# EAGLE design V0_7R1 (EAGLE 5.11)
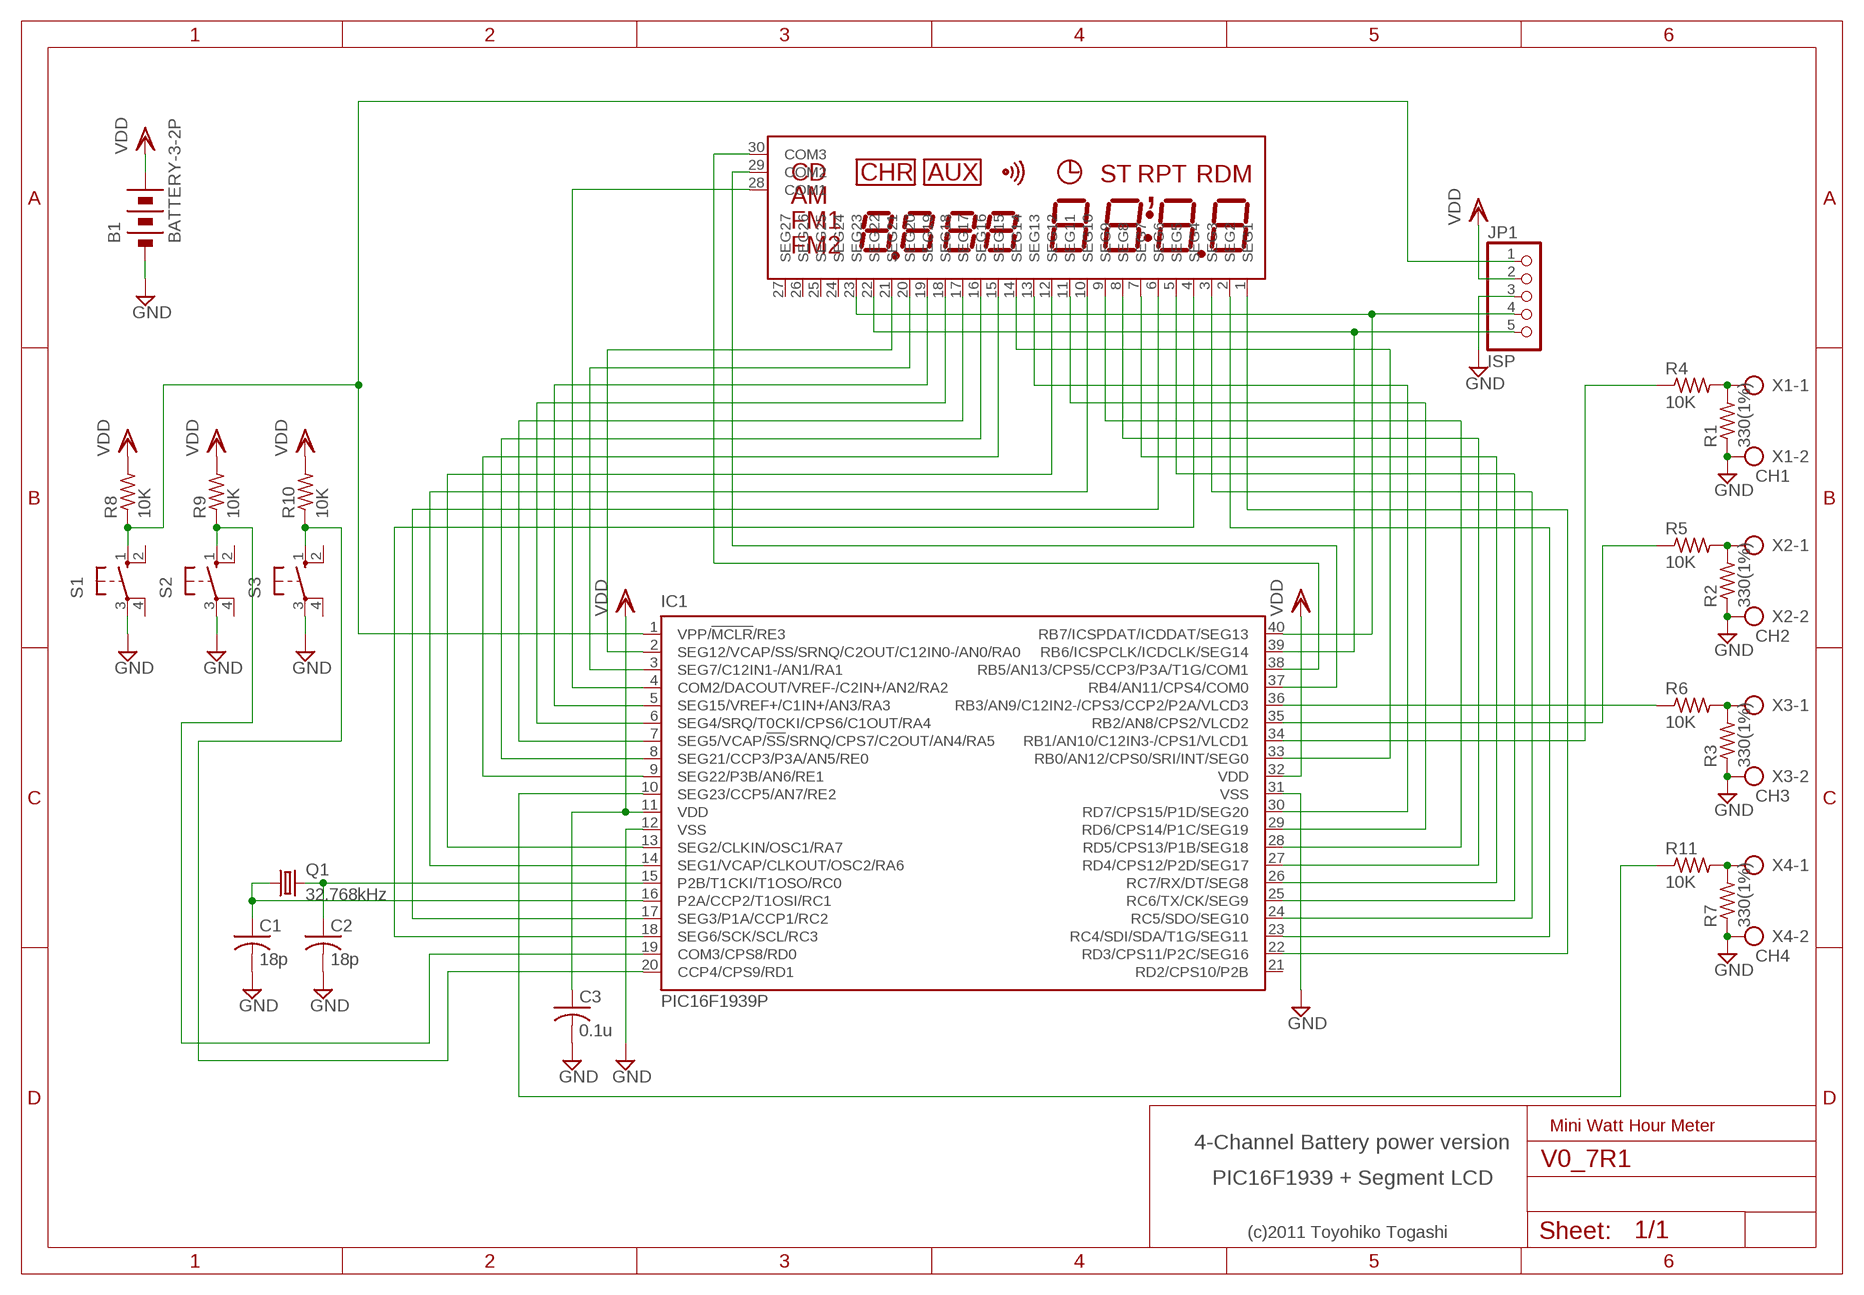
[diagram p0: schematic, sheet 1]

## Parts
B1  BATTERY-3-2P  [CONN-2P]
C1  18p  C-US025-024X044  [C025-024X044]
C2  18p  C-US025-024X044  [C025-024X044]
C3  0.1u  C-US025-024X044  [C025-024X044]
IC1  PIC16F1939P  [DIL40]
JP1  ISP  PINHD-1X5  [1X05]
LCD1  LCD-30P-AITENDO  [LCD-30P-AITENDO]
Q1  32.768kHz  CRYSTALTC38H  [TC38H]
R1  330(1%)  R-US_0204/7  [0204/7]
R2  330(1%)  R-US_0204/7  [0204/7]
R3  330(1%)  R-US_0204/7  [0204/7]
R4  10K  R-US_0204/5  [0204/5]
R5  10K  R-US_0204/5  [0204/5]
R6  10K  R-US_0204/5  [0204/5]
R7  330(1%)  R-US_0204/7  [0204/7]
R8  10K  R-US_0204/5  [0204/5]
R9  10K  R-US_0204/5  [0204/5]
R10  10K  R-US_0204/5  [0204/5]
R11  10K  R-US_0204/5  [0204/5]
S1  10-XX  [B3F-10XX]
S2  10-XX  [B3F-10XX]
S3  10-XX  [B3F-10XX]
X1  CH1  AK300/2  [AK300/2]
X2  CH2  AK300/2  [AK300/2]
X3  CH3  AK300/2  [AK300/2]
X4  CH4  AK300/2  [AK300/2]

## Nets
GND: B1.P$2(MINUS) C1.2 C2.2 C3.2 IC1.12(VSS) IC1.31(VSS) JP1.3 R1.1 R2.1 R3.1 R7.1 S1.3(P) S2.3(P) S3.3(P) X1.2 X2.2 X3.2 X4.2
N$1: IC1.37(RB4/AN11/CPS4/COM0) LCD1.29(COM2)
N$2: IC1.38(RB5/AN13/CPS5/CCP3/P3A/T1G/COM1) LCD1.30(COM3)
N$3: IC1.39(RB6/ICSPCLK/ICDCLK/SEG14) JP1.5 LCD1.22(SEG22)
N$4: IC1.2(SEG12/VCAP/SS/SRNQ/C2OUT/C12IN0-/AN0/RA0) LCD1.21(SEG21)
N$5: IC1.14(SEG1/VCAP/CLKOUT/OSC2/RA6) LCD1.10(SEG10)
N$6: IC1.13(SEG2/CLKIN/OSC1/RA7) LCD1.12(SEG12)
N$7: IC1.17(SEG3/P1A/CCP1/RC2) LCD1.6(SEG6)
N$8: IC1.6(SEG4/SRQ/T0CKI/CPS6/C1OUT/RA4) LCD1.18(SEG18)
N$9: IC1.7(SEG5/VCAP/!SS!/SRNQ/CPS7/C2OUT/AN4/RA5) LCD1.17(SEG17)
N$10: IC1.18(SEG6/SCK/SCL/RC3) LCD1.4(SEG4)
N$11: IC1.22(RD3/CPS11/P2C/SEG16) LCD1.1(SEG1)
N$12: IC1.26(RC7/RX/DT/SEG8) LCD1.7(SEG7)
N$13: IC1.25(RC6/TX/CK/SEG9) LCD1.5(SEG5)
N$14: IC1.24(RC5/SDO/SEG10) LCD1.3(SEG3)
N$15: IC1.23(RC4/SDI/SDA/T1G/SEG11) LCD1.2(SEG2)
N$16: IC1.1(VPP/!MCLR!/RE3) JP1.1 R8.1 S1.1(S)
N$17: R7.2 R11.2 X4.1
N$18: IC1.40(RB7/ICSPDAT/ICDDAT/SEG13) JP1.4 LCD1.23(SEG23)
N$19: IC1.10(SEG23/CCP5/AN7/RE2) R11.1
N$21: IC1.27(RD4/CPS12/P2D/SEG17) LCD1.8(SEG8)
N$22: IC1.28(RD5/CPS13/P1B/SEG18) LCD1.9(SEG9)
N$24: IC1.19(COM3/CPS8/RD0) R9.1 S2.1(S)
N$25: IC1.4(COM2/DACOUT/VREF-/C2IN+/AN2/RA2) LCD1.28(COM1)
N$26: IC1.29(RD6/CPS14/P1C/SEG19) LCD1.11(SEG11)
N$28: IC1.8(SEG21/CCP3/P3A/AN5/RE0) LCD1.16(SEG16)
N$29: IC1.9(SEG22/P3B/AN6/RE1) LCD1.15(SEG15)
N$31: C2.1 IC1.15(P2B/T1CKI/T1OSO/RC0) Q1.2
N$32: C1.1 IC1.16(P2A/CCP2/T1OSI/RC1) Q1.1
N$33: IC1.34(RB1/AN10/C12IN3-/CPS1/VLCD1) R4.1
N$36: IC1.20(CCP4/CPS9/RD1) R10.1 S3.1(S)
N$37: R1.2 R4.2 X1.1
N$38: IC1.33(RB0/AN12/CPS0/SRI/INT/SEG0) LCD1.14(SEG14)
N$39: R2.2 R5.2 X2.1
N$40: IC1.35(RB2/AN8/CPS2/VLCD2) R5.1
N$41: R3.2 R6.2 X3.1
N$42: IC1.36(RB3/AN9/C12IN2-/CPS3/CCP2/P2A/VLCD3) R6.1
N$45: IC1.30(RD7/CPS15/P1D/SEG20) LCD1.13(SEG13)
N$47: IC1.3(SEG7/C12IN1-/AN1/RA1) LCD1.20(SEG20)
N$51: IC1.5(SEG15/VREF+/C1IN+/AN3/RA3) LCD1.19(SEG19)
VDD: B1.P$1(PLUS) C3.1 IC1.11(VDD) IC1.32(VDD) JP1.2 R8.2 R9.2 R10.2
Unconnected: IC1.21(RD2/CPS10/P2B) LCD1.24(SEG24) LCD1.25(SEG25) LCD1.26(SEG26) LCD1.27(SEG27) S1.2(S1) S1.4(P1) S2.2(S1) S2.4(P1) S3.2(S1) S3.4(P1)

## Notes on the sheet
- Mini Watt Hour Meter
- 4-Channel Battery power version
- PIC16F1939 + Segment LCD
- (c)2011 Toyohiko Togashi

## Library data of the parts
B1 = TOG:BATTERY-3: Battery 3cell
C1-C3 = rcl:C-US: CAPACITOR, American symbol
IC1 = microchip:PIC16F193*?: Flash-Based, 8-Bit CMOS Microcontrollers wtih LCD Driver and nanoWatt XLP Technology Auto generated by make-symbol-device-package-bsdl.ulp Rev. 33 Source: http://ww1.microchip.com/downloads/en/DeviceDoc/41364D.pdf; MPN: PIC16F1939-I/P; OC_FARNELL: 1755832; OC_NEWARK: 08R1958
JP1 = pinhead:PINHD-1X5: PIN HEADER
LCD1 = TOG:LCD-30P-AITENDO
Q1 = crystal:CRYSTAL: CRYSTAL; OC_FARNELL: unknown; OC_NEWARK: unknown
R1-R11 = rcl:R-US_: RESISTOR, American symbol
S1-S3 = switch-omron:10-XX: OMRON SWITCH; MPN: B3F-1000; OC_FARNELL: 176432; OC_NEWARK: 36M3542
X1-X4 = con-ptr500:AK300/2: CONNECTOR; OC_FARNELL: unknown; OC_NEWARK: unknown

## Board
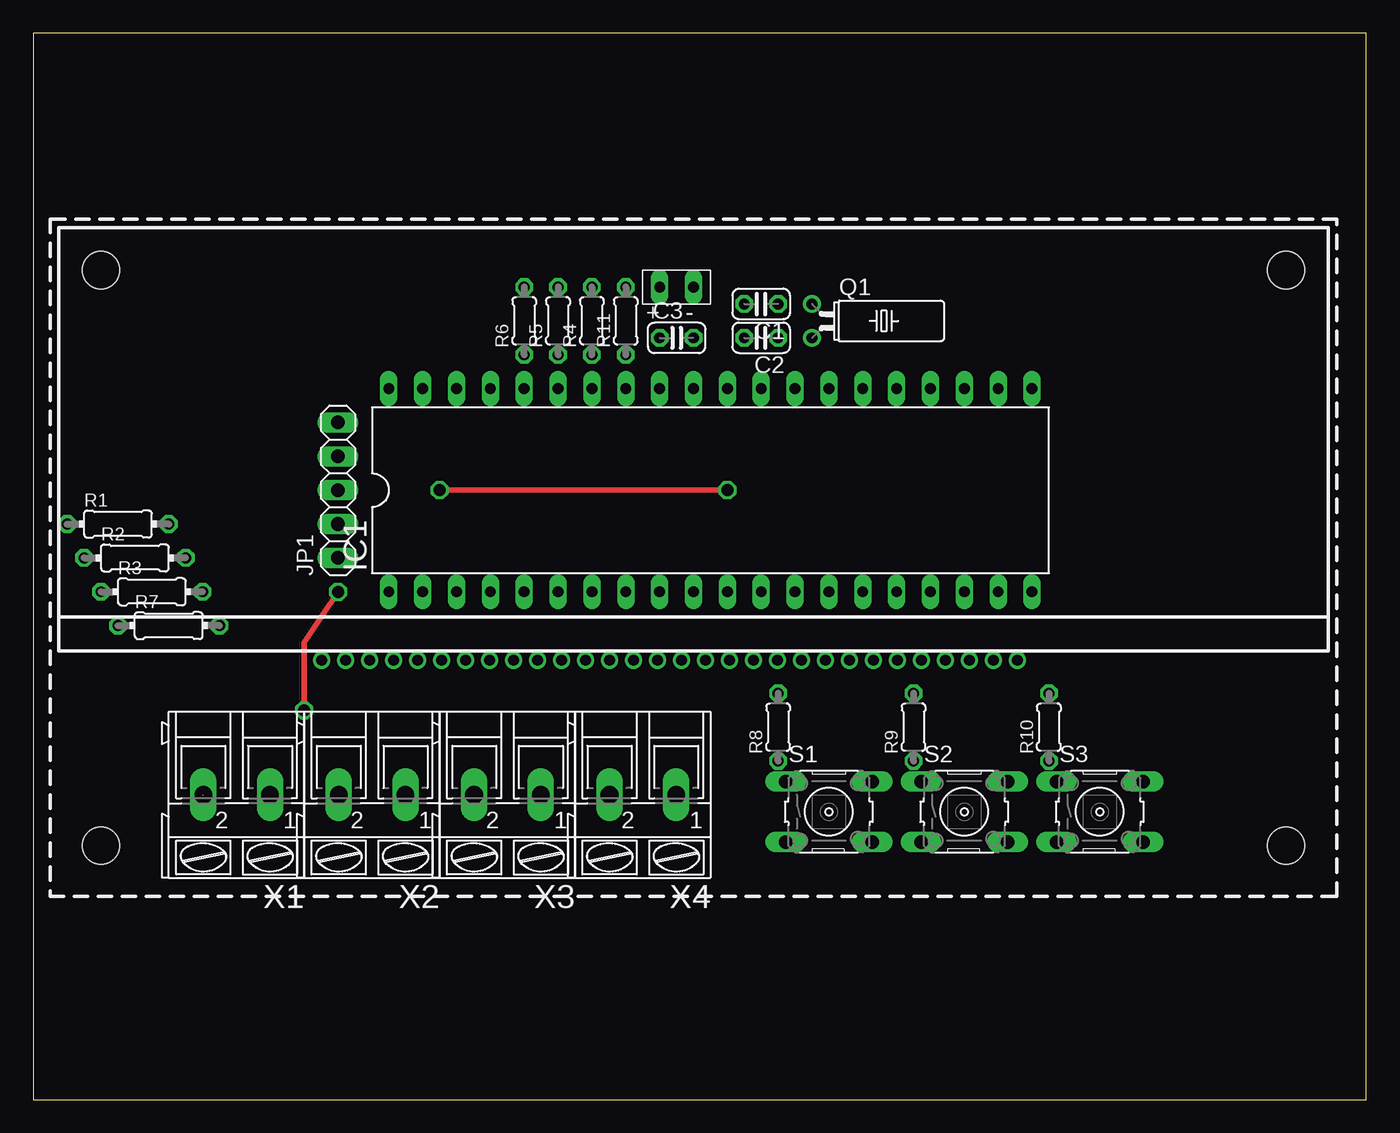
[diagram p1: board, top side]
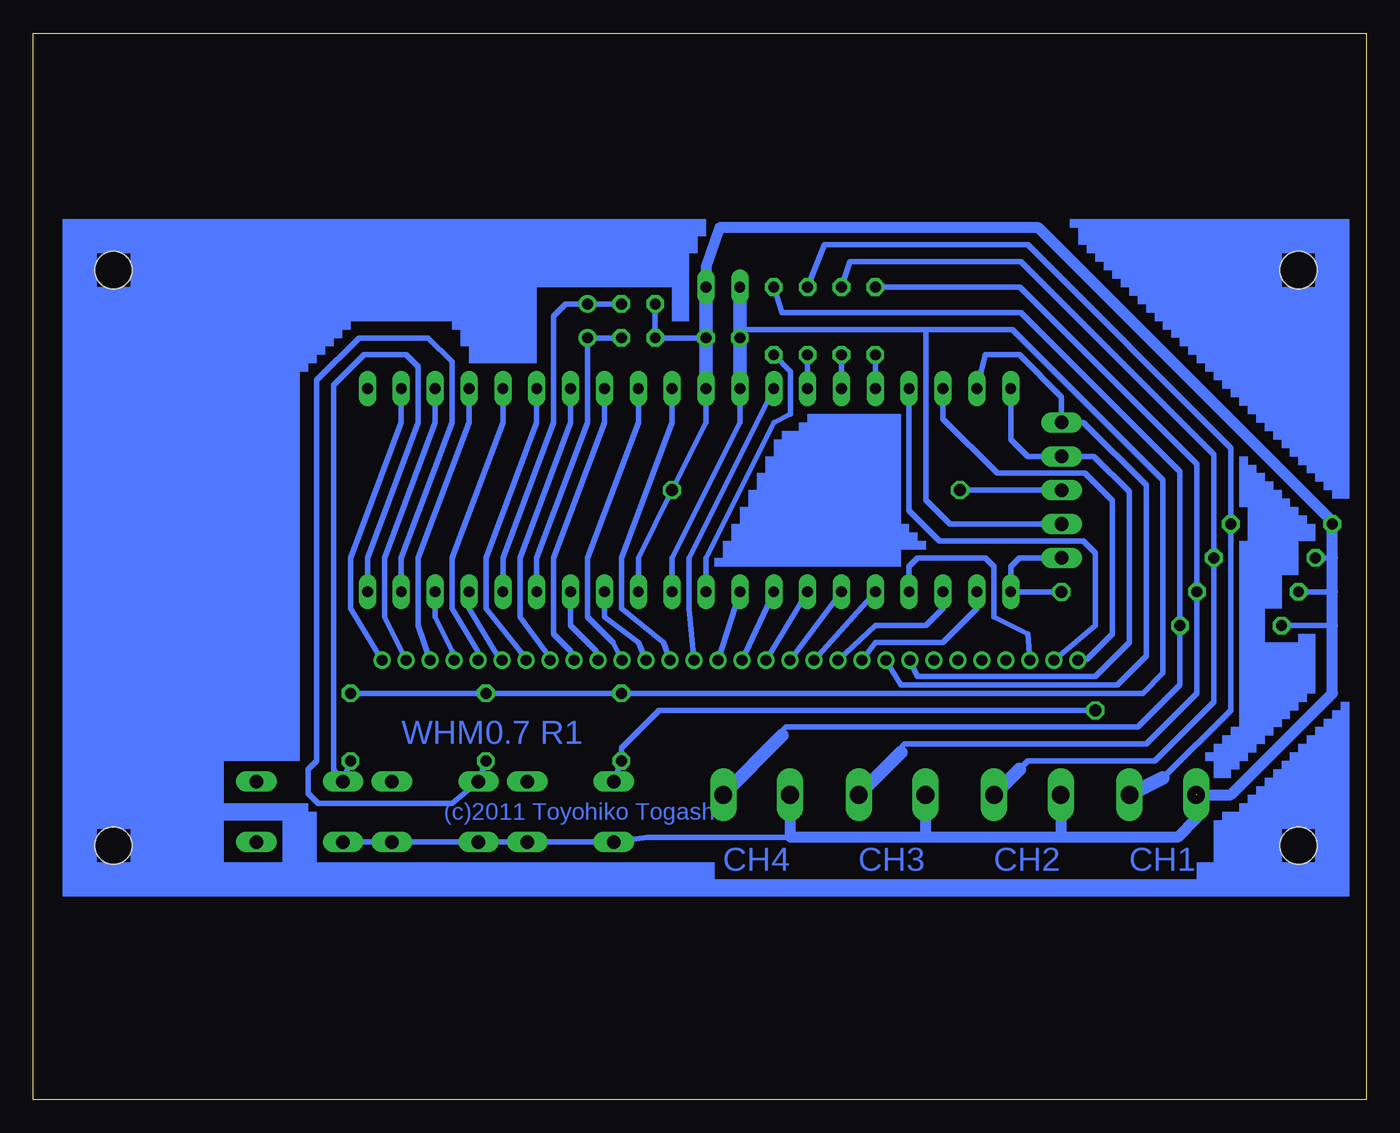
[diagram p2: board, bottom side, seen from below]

Size 100 x 80 mm. Coordinates in mm from the lower left corner, seen from the top.
Outline: 0,0 100,0 100,80 0,80 0,0
Copper layers (1*16): Top 0.035mm / dielectric 1.5mm / Bottom 0.035mm
Design rules "default": minimum track width 10mil, minimum drill 24mil, track to track 8mil, track to pad 8mil, pad to pad 8mil, via to via 8mil, smd to smd 8mil, copper to edge 40mil, drill to drill 8mil, minimum pad ring 10mil, minimum via ring 8mil, stop-mask expansion 4mil, vias tented up to drill 0mil, thermal gap 10mil
Holes 2.8 mm at 5.08,19.05 93.98,19.05 93.98,62.23 5.08,62.23

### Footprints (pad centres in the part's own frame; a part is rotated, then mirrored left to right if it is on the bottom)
CONN-2P = drill 0.8 long: P$1 1.27,0; P$2 -1.27,0
C025-024X044 = drill 0.813 octagon: 1 -1.27,0; 2 1.27,0
DIL40 = drill 0.813 long: 1 -24.13,-7.62; 2 -21.59,-7.62; 3 -19.05,-7.62; 4 -16.51,-7.62; 5 -13.97,-7.62; 6 -11.43,-7.62; 7 -8.89,-7.62; 8 -6.35,-7.62; 9 -3.81,-7.62; 10 -1.27,-7.62; 11 1.27,-7.62; 12 3.81,-7.62; 13 6.35,-7.62; 14 8.89,-7.62; 15 11.43,-7.62; 16 13.97,-7.62; 17 16.51,-7.62; 18 19.05,-7.62; 19 21.59,-7.62; 20 24.13,-7.62; 21 24.13,7.62; 22 21.59,7.62; 23 19.05,7.62; 24 16.51,7.62; 25 13.97,7.62; 26 11.43,7.62; 27 8.89,7.62; 28 6.35,7.62; 29 3.81,7.62; 30 1.27,7.62; 31 -1.27,7.62; 32 -3.81,7.62; 33 -6.35,7.62; 34 -8.89,7.62; 35 -11.43,7.62; 36 -13.97,7.62; 37 -16.51,7.62; 38 -19.05,7.62; 39 -21.59,7.62; 40 -24.13,7.62
1X05 = drill 1.016 long: 1 -5.08,0; 2 -2.54,0; 3 0,0; 4 2.54,0; 5 5.08,0
LCD-30P-AITENDO = drill 0.8 round: 1 24.3,-15.3; 2 22.5,-15.3; 3 20.7,-15.3; 4 18.9,-15.3; 5 17.1,-15.3; 6 15.3,-15.3; 7 13.5,-15.3; 8 11.7,-15.3; 9 9.9,-15.3; 10 8.1,-15.3; 11 6.3,-15.3; 12 4.5,-15.3; 13 2.7,-15.3; 14 0.9,-15.3; 15 -0.9,-15.3; 16 -2.7,-15.3; 17 -4.5,-15.3; 18 -6.3,-15.3; 19 -8.1,-15.3; 20 -9.9,-15.3; 21 -11.7,-15.3; 22 -13.5,-15.3; 23 -15.3,-15.3; 24 -17.1,-15.3; 25 -18.9,-15.3; 26 -20.7,-15.3; 27 -22.5,-15.3; 28 -24.3,-15.3; 29 -26.1,-15.3; 30 -27.9,-15.3
TC38H = drill 0.813 round: 1 -1.27,0; 2 1.27,0
0204/7 = drill 0.813 octagon: 1 -3.81,0; 2 3.81,0
0204/5 = drill 0.813 octagon: 1 -2.54,0; 2 2.54,0
B3F-10XX = drill 1.016 long: 1 -3.251,2.261; 2 3.251,2.261; 3 -3.251,-2.261; 4 3.251,-2.261
AK300/2 = drill 1.321 long: 1 -2.515,0; 2 2.489,0

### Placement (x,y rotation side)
B1  48.26,60.96 180 top
C1  54.61,59.69 180 top
C2  54.61,57.15 180 top
C3  48.26,57.15 0 top
IC1  50.8,45.72 0 top
JP1  22.86,45.72 90 top
LCD1  49.53,48.26 0 top
Q1  58.42,58.42 270 top
R1  6.35,43.18 0 top
R2  7.62,40.64 0 top
R3  8.89,38.1 0 top
R4  41.91,58.42 90 top
R5  39.37,58.42 90 top
R6  36.83,58.42 90 top
R7  10.16,35.56 0 top
R8  55.88,27.94 90 top
R9  66.04,27.94 90 top
R10  76.2,27.94 90 top
R11  44.45,58.42 90 top
S1  59.69,21.59 0 top
S2  69.85,21.59 0 top
S3  80.01,21.59 0 top
X1  15.24,22.86 180 top
X2  25.4,22.86 180 top
X3  35.56,22.86 180 top
X4  45.72,22.86 180 top

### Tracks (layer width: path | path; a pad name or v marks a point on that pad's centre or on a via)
GND  (via drill 0.9)  (1 unrouted)
  Top 0.406: v52.07,45.72 v30.48,45.72
  Bottom 0.406: IC1.31 49.53,50.8 v52.07,45.72 54.61,40.64 IC1.12 | C1.2 C2.2 C3.2 | 12.7,22.86 12.7,24.13 | 43.18,19.68 53.98,19.68 S1.3 S2.3 S3.3 | v30.48,45.72 JP1.3 | 2.54,35.56 R7.1 | 2.54,38.1 R3.1 | 2.54,40.64 R2.1
  Bottom 0.813: 22.86,19.68 14.14,19.68 12.72,21.12 X1.2 10.16,22.86 2.54,30.48 2.54,35.56 2.54,38.1 2.54,40.64 R1.1 2.54,43.36 24.58,65.41 48.51,65.41 49.53,62.48 B1.P$2 | 22.86,19.68 33.02,19.68 | 33.02,19.68 43.18,19.68 X4.2 | 22.86,19.68 X2.2 | 33.02,19.68 X3.2
  Bottom 1.016: IC1.31 C3.2 B1.P$2
N$1
  Bottom 0.406: LCD1.29 20.32,35.56 20.32,41.01 21.22,41.91 32,41.91 34.29,44.2 IC1.37
N$2
  Bottom 0.406: IC1.38 31.75,51.06 27.68,46.99 21.11,46.99 19.05,44.94 19.05,34.92 20.95,33.02 LCD1.30
N$3
  Bottom 0.406: IC1.39 28.57,55.88 26.04,55.88 22.86,52.7 JP1.5 21.21,50.8 16.51,46.1 16.51,33.28 18.68,31.11 34.92,31.11 LCD1.22
N$4
  Bottom 0.406: IC1.2 29.21,36.83 31.75,34.29 36.83,34.29 LCD1.21
N$5
  Bottom 0.406: LCD1.10 57.78,33.66 59.69,35.56 IC1.14
N$6
  Bottom 0.406: LCD1.12 54.61,34.29 57.15,36.2 IC1.13
N$7
  Bottom 0.406: LCD1.6 65.41,33.66 67.31,36.83 IC1.17
N$8
  Bottom 0.406: IC1.6 LCD1.18
N$9
  Bottom 0.406: IC1.7 LCD1.17
N$10
  Bottom 0.406: LCD1.4 68.58,33.66 69.85,36.2 IC1.18
N$11
  Bottom 0.406: IC1.22 72.39,50.8 76.2,40.64 76.2,36.83 LCD1.1
N$12
  Bottom 0.406: LCD1.7 63.5,33.66 66.04,36.83 66.04,40.64 62.23,50.8 IC1.26
N$13
  Bottom 0.406: LCD1.5 66.67,33.66 68.58,36.83 68.58,40.64 64.77,50.8 IC1.25
N$14
  Bottom 0.406: LCD1.3 71.12,35.56 71.12,40.64 67.31,50.8 IC1.24
N$15
  Bottom 0.406: LCD1.2 73.66,36.2 73.66,40.64 69.85,50.8 IC1.23
N$16  (via drill 0.9)
  Top 0.406: v20.32,29.21 20.32,34.29 v22.86,38.1
  Bottom 0.406: S1.1 R8.1 55.88,26.37 53.04,29.21 v20.32,29.21 | v22.86,38.1 IC1.1 26.67,40.01 26.04,40.64 JP1.1
N$17
  Bottom 0.406: X4.1 48.26,22.86 43.55,27.94 17.14,27.94 13.97,31.11 R7.2 13.97,47.11 25.91,59.05 43.81,59.05 R11.2
  Bottom 1.016: 48.26,22.86 43.81,27.3
N$18
  Bottom 0.406: IC1.40 26.67,49.53 25.4,48.26 JP1.4 20.42,48.26 17.78,45.62 17.78,34.29 20.32,31.75 33.66,31.75 LCD1.23
N$19
  Bottom 0.406: R11.1 43.18,54.61 43.18,51.44 44.45,50.8 49.53,40.64 IC1.10
N$20
  Bottom 1.016: 27.94,22.86 26.04,24.77
N$21
  Bottom 0.406: LCD1.8 61.59,33.66 63.5,36.2 63.5,40.64 59.69,50.8 IC1.27
N$22
  Bottom 0.406: LCD1.9 59.69,33.66 60.96,34.92 60.96,40.64 57.15,50.8 IC1.28
N$23
  Bottom 1.016: 38.1,22.86 34.92,26.04
N$24
  Bottom 0.406: R9.1 S2.1 68.58,22.23 78.64,22.23 79.38,22.96 79.38,24.77 78.74,25.4 78.74,53.98 75.56,57.15 70.38,57.15 68.58,55.35 68.58,50.8 72.39,40.64 IC1.19
N$25
  Bottom 0.406: LCD1.28 25.4,34.92 27.94,36.2 27.94,40.01 28.57,40.64 33.66,40.64 34.29,40.01 IC1.4
N$26
  Bottom 0.406: LCD1.11 56.52,34.29 58.42,36.2 58.42,40.64 54.61,50.8 IC1.29
N$28
  Bottom 0.406: IC1.8 LCD1.16
N$29
  Bottom 0.406: IC1.9 LCD1.15
N$31
  Bottom 0.406: C2.1 Q1.2 58.42,50.8 62.23,40.64 IC1.15
N$32
  Bottom 0.406: C1.1 Q1.1 60.06,59.69 60.96,58.79 60.96,50.8 64.77,40.64 IC1.16
N$33
  Bottom 0.406: IC1.34 R4.1
N$36
  Bottom 0.406: R10.1 S3.1 77.47,24.77 77.47,53.59 75.18,55.88 72.02,55.88 71.12,54.98 71.12,50.8 74.93,40.64 IC1.20
N$37
  Bottom 0.406: X1.1 15.24,24.13 10.16,29.21 R1.2 10.16,48.9 25.4,64.14 40.64,64.14 R4.2
  Bottom 1.016: 17.78,22.86 15.24,24.13
N$38
  Bottom 0.406: LCD1.14 50.8,36.83 50.8,40.64 IC1.33
N$39
  Bottom 0.406: X2.1 25.4,25.4 15.88,25.4 11.43,29.84 R2.2 11.43,48.38 25.91,62.87 38.73,62.87 R5.2
N$40
  Bottom 0.406: IC1.35 R5.1
N$41
  Bottom 0.406: X3.1 34.66,26.67 16.51,26.67 12.7,30.48 R3.2 12.7,47.67 25.99,60.96 R6.2
N$42
  Bottom 0.406: IC1.36 R6.1
N$45
  Bottom 0.406: LCD1.13 52.7,34.29 55.88,36.83 55.88,40.64 52.07,50.8 IC1.30
N$47
  Bottom 0.406: IC1.3 31.75,36.83 33.02,35.56 36.83,35.56 LCD1.20
N$51
  Bottom 0.406: IC1.5 LCD1.19
VDD
  Bottom 0.406: IC1.32 46.99,50.8 52.07,40.64 IC1.11 | R10.2 R9.2 R8.2 16.77,30.48 15.24,32.01 15.24,46.48 26.55,57.78 33.02,57.78 | JP1.2 31.22,43.18 33.02,44.98 33.02,57.78 | 33.02,57.78 46.99,57.78
  Bottom 0.813: B1.P$1 46.99,61.33
  Bottom 1.016: IC1.32 C3.1 46.99,57.78 B1.P$1
(copper drawn outside any net)
  shapes: Bottom area x116

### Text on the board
Bottom: WHM0.7 R1 | (c)2011 Toyohiko Togashi | CH1 | CH2 | CH3 | CH4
